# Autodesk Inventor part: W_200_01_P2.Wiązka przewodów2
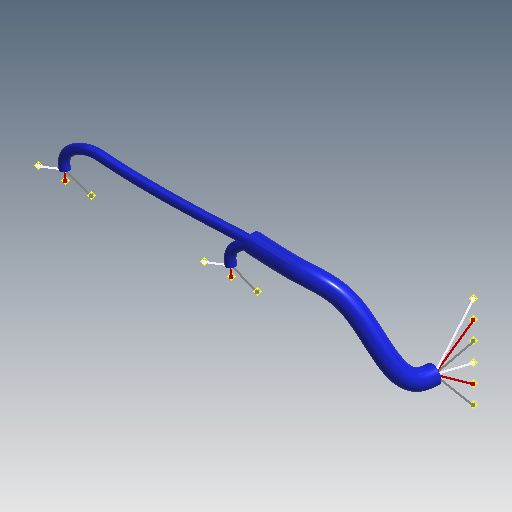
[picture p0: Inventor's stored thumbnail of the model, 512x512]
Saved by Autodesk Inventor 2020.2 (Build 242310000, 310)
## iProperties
Key:2|1|1|0|4|0|0|0|2|0|0|0|Level:2: <CableProperty entityType="Connector" version="1.0"><ID editable="" value=""/><UserDefined/><Name editable="True" value=""/><Refdes editable="True" value="S_150
Key:2|1|1|0|4|0|0|0|3|0|0|0|Level:2: <CableProperty entityType="Connector" version="1.0"><ID editable="" value=""/><UserDefined/><Name editable="True" value=""/><Refdes editable="True" value="S_150
Key:2|1|1|0|4|0|0|0|8|0|0|0|Level:2: <CableProperty entityType="Connector" version="1.0"><ID editable="" value=""/><UserDefined/><Name editable="True" value=""/><Refdes editable="True" value="LISTW
GlobalPropertyList: <PropertyList/>
Manager: www.cadconsulting.pl
Company: Fabian Stasiak CAD Consulting
Created: 2014-09
Part Number: W_200_01_P2.Wiązka przewodów2
Material: Ogólne
Document SubType Name: Modelowanie
Designer: F.Stasiak
Appearance: Ogólne
Catalog Web Link: www.expertbooks.pl
Author: F.Stasiak
Subject: Zbiór ćwiczeń. Autodesk Inventor 2020. Kurs Professional
## Parameters: d2 = 0, d3 = 0, d4 = 0, d5 = 0, d6 = 0, d7 = 0
